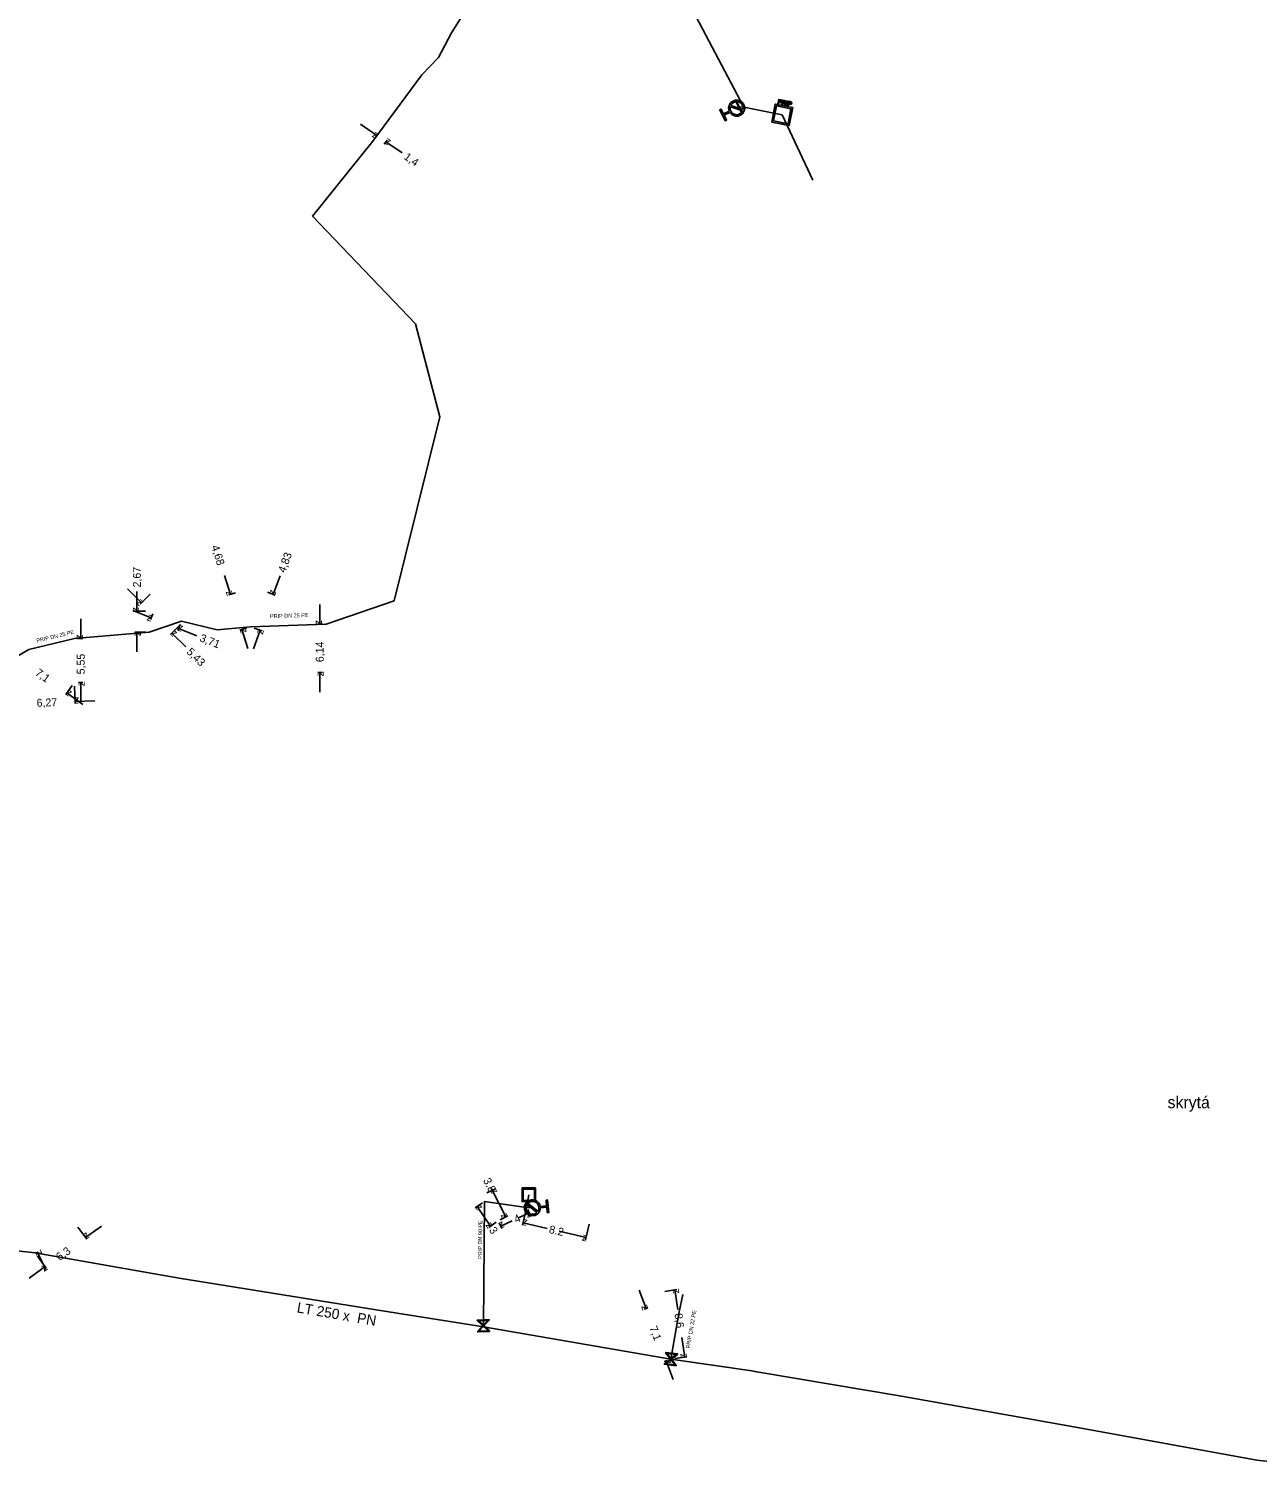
# Model space of a CAD drawing. Extents: x -643842 to -636370, y -1119190 to -1110210.
# Drawn here: x -641528.3 to -641372.7, y -1114327.3 to -1114143.7 of the extents above; entities that cross this region are included whole.
import ezdxf

# ---------------------------------------------------------------- set-up
doc = ezdxf.new("R2010")
doc.units = 0
for name, color, linetype in [('22', 7, 'Continuous'), ('7', 7, 'Continuous'), ('Default', 7, 'Continuous'), ('Level 10', 7, 'Continuous'), ('Level 16', 7, 'Continuous'), ('Level 18', 7, 'Continuous'), ('Level 20', 7, 'Continuous'), ('Level 21', 7, 'Continuous'), ('Level 23', 7, 'Continuous'), ('Level 33', 7, 'Continuous')]:
    doc.layers.add(name, color=color, linetype=linetype)

msp = doc.modelspace()

# ---------------------------------------------------------------- linework, layer by layer
at = {"layer": 'Default'}
for points in [[(-641439.58, -1114154.04), (-641439.72, -1114153.71), (-641439.6, -1114153.36), (-641439.47, -1114152.97), (-641439.09, -1114152.78), (-641438.72, -1114152.6), (-641438.33, -1114152.73), (-641437.94, -1114152.86), (-641437.75, -1114153.24), (-641437.57, -1114153.6), (-641437.7, -1114154), (-641437.83, -1114154.39), (-641438.2, -1114154.57), (-641438.57, -1114154.76), (-641438.97, -1114154.63), (-641439.32, -1114154.52), (-641439.5, -1114154.21)], [(-641439.45, -1114153.51), (-641439.51, -1114153.78), (-641439.38, -1114154.04), (-641439.23, -1114154.35), (-641438.91, -1114154.45), (-641438.59, -1114154.56), (-641438.29, -1114154.41), (-641438.03, -1114154.28), (-641437.91, -1114154.02)], [(-641437.85, -1114153.85), (-641437.79, -1114153.58), (-641437.92, -1114153.32), (-641438.07, -1114153.02), (-641438.39, -1114152.91), (-641438.71, -1114152.8), (-641439.01, -1114152.96), (-641439.27, -1114153.08), (-641439.39, -1114153.34)], [(-641433.12, -1114152.61), (-641433.06, -1114152.62), (-641433.04, -1114152.63), (-641433, -1114152.65), (-641432.97, -1114152.67), (-641432.95, -1114152.69), (-641432.94, -1114152.73), (-641432.93, -1114152.77), (-641432.94, -1114152.81), (-641432.95, -1114152.89), (-641433, -1114152.93), (-641433.06, -1114152.97), (-641433.18, -1114152.94)], [(-641433.16, -1114152.88), (-641433.09, -1114152.89), (-641433.06, -1114152.87), (-641433.02, -1114152.85), (-641433.01, -1114152.8), (-641433.01, -1114152.76), (-641433.02, -1114152.74), (-641433.03, -1114152.71), (-641433.06, -1114152.7), (-641433.08, -1114152.69), (-641433.13, -1114152.68)], [(-641432.59, -1114153.17), (-641432.61, -1114153.12), (-641432.63, -1114153.09), (-641432.64, -1114153.05), (-641432.66, -1114153.04), (-641432.67, -1114153.03), (-641432.69, -1114153.02), (-641432.7, -1114153.01), (-641432.73, -1114153.01)], [(-641432.64, -1114152.96), (-641432.59, -1114152.97), (-641432.56, -1114152.96), (-641432.53, -1114152.96), (-641432.51, -1114152.94), (-641432.49, -1114152.92), (-641432.49, -1114152.89), (-641432.48, -1114152.85), (-641432.5, -1114152.82), (-641432.53, -1114152.79), (-641432.59, -1114152.78)], [(-641432.58, -1114152.71), (-641432.5, -1114152.73), (-641432.47, -1114152.75), (-641432.43, -1114152.77), (-641432.42, -1114152.82), (-641432.4, -1114152.86), (-641432.41, -1114152.9), (-641432.42, -1114152.97), (-641432.47, -1114153), (-641432.51, -1114153.03), (-641432.6, -1114153.03), (-641432.57, -1114153.05), (-641432.56, -1114153.06), (-641432.53, -1114153.1), (-641432.51, -1114153.15)], [(-641431.86, -1114152.85), (-641431.81, -1114152.87), (-641431.78, -1114152.88), (-641431.74, -1114152.89), (-641431.71, -1114152.92), (-641431.69, -1114152.94), (-641431.68, -1114152.98), (-641431.67, -1114153.02), (-641431.68, -1114153.06), (-641431.69, -1114153.13), (-641431.74, -1114153.17), (-641431.8, -1114153.21), (-641431.92, -1114153.19)], [(-641431.91, -1114153.12), (-641431.83, -1114153.14), (-641431.8, -1114153.12), (-641431.76, -1114153.1), (-641431.75, -1114153.05), (-641431.75, -1114153.01), (-641431.76, -1114152.98), (-641431.77, -1114152.96), (-641431.8, -1114152.94), (-641431.82, -1114152.93), (-641431.87, -1114152.92)], [(-641463.52, -1114292.94), (-641463.52, -1114293.3), (-641463.75, -1114293.58), (-641464.02, -1114293.9), (-641464.43, -1114293.94), (-641464.84, -1114293.98), (-641465.16, -1114293.72), (-641465.48, -1114293.46), (-641465.52, -1114293.04), (-641465.56, -1114292.63), (-641465.3, -1114292.31), (-641465.04, -1114291.99), (-641464.62, -1114291.95), (-641464.21, -1114291.91), (-641463.89, -1114292.17), (-641463.6, -1114292.4), (-641463.54, -1114292.76)], [(-641465.21, -1114292.5), (-641465.36, -1114292.74), (-641465.33, -1114293.02), (-641465.3, -1114293.36), (-641465.04, -1114293.57), (-641464.78, -1114293.79), (-641464.44, -1114293.75), (-641464.16, -1114293.73), (-641463.96, -1114293.53)], [(-641463.84, -1114293.39), (-641463.69, -1114293.16), (-641463.71, -1114292.87), (-641463.75, -1114292.53), (-641464.01, -1114292.32), (-641464.27, -1114292.1), (-641464.6, -1114292.14), (-641464.89, -1114292.16), (-641465.09, -1114292.36)]]:
    msp.add_open_spline(points, degree=3, dxfattribs=at)
at = {"layer": 'Level 10'}
for points in [[(-641486.28, -1114155.7), (-641484.22, -1114157.13)], [(-641484.44, -1114157.43), (-641484.08, -1114156.92)], [(-641483.29, -1114158.23), (-641482.93, -1114157.72)], [(-641481.02, -1114159.35), (-641483.07, -1114157.93)], [(-641503.52, -1114212.87), (-641502.76, -1114215.25)], [(-641496.49, -1114212.9), (-641497.35, -1114215.25)], [(-641515.82, -1114214.57), (-641514.05, -1114216.33)], [(-641514.62, -1114214.87), (-641514.62, -1114217.37)], [(-641512.96, -1114215.23), (-641514.22, -1114216.51)], [(-641502.12, -1114215.04), (-641502.99, -1114215.32)], [(-641498.09, -1114214.98), (-641497.11, -1114215.34)], [(-641515.13, -1114217.29), (-641512.8, -1114218.21)], [(-641513.55, -1114217.37), (-641514.87, -1114217.37)], [(-641512.61, -1114217.73), (-641512.9, -1114218.44)], [(-641491.46, -1114216.52), (-641491.46, -1114219.02)], [(-641521.73, -1114218.35), (-641521.73, -1114220.85)], [(-641509.1, -1114219.06), (-641510.37, -1114220.33)], [(-641509.17, -1114219.1), (-641509.45, -1114219.81)], [(-641507.03, -1114220.5), (-641509.36, -1114219.58)], [(-641500.69, -1114219.5), (-641501.57, -1114219.78)], [(-641500.57, -1114222.09), (-641501.33, -1114219.7)], [(-641499.86, -1114222.14), (-641499, -1114219.79)], [(-641499.75, -1114219.52), (-641498.77, -1114219.87)], [(-641491.13, -1114219.02), (-641491.71, -1114219.02)], [(-641522.03, -1114220.85), (-641521.48, -1114220.85)], [(-641513.55, -1114220.04), (-641514.87, -1114220.04)], [(-641514.62, -1114222.54), (-641514.62, -1114220.04)], [(-641508.42, -1114221.92), (-641510.19, -1114220.16)], [(-641491.13, -1114225.16), (-641491.71, -1114225.16)], [(-641491.46, -1114227.66), (-641491.46, -1114225.16)], [(-641522.82, -1114226.8), (-641523.64, -1114227.94)], [(-641522.51, -1114226.9), (-641522.42, -1114229.06)], [(-641522.03, -1114226.4), (-641521.48, -1114226.4)], [(-641521.73, -1114228.9), (-641521.73, -1114226.4)], [(-641521.46, -1114229.2), (-641523.49, -1114227.73)], [(-641519.94, -1114228.72), (-641522.43, -1114228.81)], [(-641470.31, -1114291.06), (-641469.34, -1114290.57)], [(-641469.78, -1114290.37), (-641469.61, -1114290.71)], [(-641469.61, -1114290.71), (-641467.9, -1114294.1)], [(-641470.83, -1114292.3), (-641471.78, -1114292.96)], [(-641469.82, -1114295.25), (-641471.54, -1114292.79)], [(-641465.32, -1114293.18), (-641465.77, -1114295.15)], [(-641465.12, -1114293.16), (-641464.79, -1114293.86)], [(-641519.1, -1114295.25), (-641521.13, -1114296.71)], [(-641469.12, -1114294.76), (-641470.06, -1114295.42)], [(-641468.74, -1114294.86), (-641468.41, -1114295.57)], [(-641468.6, -1114294.46), (-641467.63, -1114293.97)], [(-641467.07, -1114294.6), (-641468.54, -1114295.29)], [(-641466.27, -1114294.23), (-641464.92, -1114293.59)], [(-641462.67, -1114295.56), (-641465.71, -1114294.86)], [(-641457.33, -1114295.02), (-641457.78, -1114297)], [(-641522.08, -1114295.39), (-641520.98, -1114296.91)], [(-641461.13, -1114295.91), (-641457.72, -1114296.7)], [(-641526.15, -1114300.78), (-641527.25, -1114298.54)], [(-641527.04, -1114298.43), (-641527.03, -1114298.43)], [(-641528.27, -1114301.84), (-641526.24, -1114300.39)], [(-641527.2, -1114299.06), (-641526.1, -1114300.59)], [(-641451.02, -1114303.38), (-641450.12, -1114305.71)], [(-641447.74, -1114303.53), (-641446.23, -1114303.3)], [(-641446.11, -1114305.82), (-641446.48, -1114303.34)], [(-641449.99, -1114305.66), (-641450.36, -1114305.8)], [(-641445.59, -1114309.37), (-641445.22, -1114311.85)], [(-641446.48, -1114312.03), (-641444.97, -1114311.81)], [(-641447.44, -1114312.29), (-641447.81, -1114312.43)], [(-641446.68, -1114314.67), (-641447.58, -1114312.34)]]:
    msp.add_lwpolyline(points, dxfattribs=at)
at = {"layer": 'Level 16'}
for points in [[(-641438.66, -1114152.8), (-641437.99, -1114154.14), (-641438.08, -1114154.18), (-641438.75, -1114152.84), (-641438.66, -1114152.8)], [(-641469.95, -1114308.61), (-641471.45, -1114308.67), (-641471.45, -1114308.6), (-641471.36, -1114308.51), (-641470.79, -1114307.89), (-641471.5, -1114307.23), (-641471.51, -1114307.17), (-641470.01, -1114307.11), (-641470.01, -1114307.18), (-641470.67, -1114307.89), (-641470.05, -1114308.46), (-641469.95, -1114308.54), (-641469.95, -1114308.61)], [(-641471.35, -1114307.25), (-641470.73, -1114307.83), (-641470.16, -1114307.21), (-641471.35, -1114307.25)], [(-641470.11, -1114308.52), (-641470.73, -1114307.95), (-641471.3, -1114308.57), (-641470.11, -1114308.52)], [(-641446.32, -1114312.94), (-641447.81, -1114312.76), (-641447.8, -1114312.69), (-641447.7, -1114312.62), (-641447.04, -1114312.1), (-641447.63, -1114311.34), (-641447.63, -1114311.27), (-641446.14, -1114311.46), (-641446.15, -1114311.52), (-641446.91, -1114312.12), (-641446.4, -1114312.78), (-641446.31, -1114312.88), (-641446.32, -1114312.94)], [(-641447.49, -1114311.38), (-641446.97, -1114312.05), (-641446.3, -1114311.53), (-641447.49, -1114311.38)], [(-641446.47, -1114312.83), (-641446.98, -1114312.17), (-641447.64, -1114312.69), (-641446.47, -1114312.83)]]:
    msp.add_lwpolyline(points, dxfattribs=at)
at = {"layer": 'Level 18'}
for points in [[(-641431.54, -1114153.6), (-641431.99, -1114155.88), (-641434.21, -1114155.45), (-641433.76, -1114153.17), (-641431.54, -1114153.6)], [(-641433.61, -1114153.4), (-641433.98, -1114155.29), (-641432.14, -1114155.65), (-641431.77, -1114153.76), (-641433.61, -1114153.4)], [(-641433.44, -1114153.13), (-641433.33, -1114152.57), (-641433.12, -1114152.61)], [(-641433.18, -1114152.94), (-641433.32, -1114152.91), (-641433.37, -1114153.14), (-641433.44, -1114153.13)], [(-641433.13, -1114152.68), (-641433.27, -1114152.65), (-641433.31, -1114152.85)], [(-641433.31, -1114152.85), (-641433.16, -1114152.88)], [(-641432.94, -1114153.23), (-641432.83, -1114152.66), (-641432.58, -1114152.71)], [(-641432.73, -1114153.01), (-641432.81, -1114152.99), (-641432.86, -1114153.24), (-641432.94, -1114153.23)], [(-641432.59, -1114152.78), (-641432.77, -1114152.74), (-641432.8, -1114152.93)], [(-641432.8, -1114152.93), (-641432.64, -1114152.96)], [(-641432.51, -1114153.15), (-641432.44, -1114153.32), (-641432.54, -1114153.31), (-641432.59, -1114153.17)], [(-641432.37, -1114153.34), (-641432.26, -1114152.78), (-641432.19, -1114152.79), (-641432.29, -1114153.35), (-641432.37, -1114153.34)], [(-641432.18, -1114153.38), (-641432.07, -1114152.81), (-641431.86, -1114152.85)], [(-641431.92, -1114153.19), (-641432.06, -1114153.16), (-641432.11, -1114153.39), (-641432.18, -1114153.38)], [(-641431.87, -1114152.92), (-641432.01, -1114152.89), (-641432.05, -1114153.1)], [(-641432.05, -1114153.1), (-641431.91, -1114153.12)], [(-641464.13, -1114290.42), (-641464.13, -1114292.16), (-641465.82, -1114292.16), (-641465.82, -1114290.42), (-641464.13, -1114290.42)], [(-641465.68, -1114290.57), (-641465.68, -1114292.01), (-641464.27, -1114292.01), (-641464.27, -1114290.57), (-641465.68, -1114290.57)]]:
    msp.add_lwpolyline(points, dxfattribs=at)
at = {"layer": 'Level 21'}
for points in [[(-641457.53, -1114115.49), (-641457.43, -1114115.74), (-641447.29, -1114135.38), (-641446.98, -1114135.99), (-641437.76, -1114153.57), (-641432.87, -1114154.52)], [(-641349.91, -1114327.29), (-641351.84, -1114327.15), (-641372.75, -1114324.91), (-641395.95, -1114320.67), (-641417.77, -1114316.82), (-641436.1, -1114313.72), (-641436.74, -1114313.61), (-641446.97, -1114312.11), (-641470.72, -1114308.04), (-641484.31, -1114305.87), (-641509.25, -1114301.85), (-641527.49, -1114298.65), (-641532.99, -1114298.05), (-641533, -1114298.05)]]:
    msp.add_lwpolyline(points, dxfattribs=at)
at = {"layer": 'Level 23'}
for points in [[(-641458.89, -1114116.02), (-641458.87, -1114116.12), (-641459.97, -1114120.78), (-641462.47, -1114124.6), (-641474.77, -1114144.15), (-641476.4, -1114147.27), (-641478.54, -1114149.45), (-641484.72, -1114157.84), (-641492.36, -1114167.36), (-641479.34, -1114180.99), (-641476.26, -1114192.79), (-641482.04, -1114216.07), (-641490.63, -1114219.02), (-641500.21, -1114219.35), (-641504.45, -1114219.75), (-641508.98, -1114218.64), (-641513.05, -1114220.04), (-641522.53, -1114220.85), (-641528.29, -1114222.24)], [(-641437.76, -1114153.57), (-641438.37, -1114153.49), (-641438.65, -1114153.68)], [(-641432.87, -1114154.52), (-641429, -1114162.8)], [(-641528.29, -1114222.24), (-641536.38, -1114226.93)], [(-641470.72, -1114308.04), (-641470.73, -1114307.89), (-641470.59, -1114292.13), (-641465.25, -1114292.89), (-641464.97, -1114291.29)], [(-641465.25, -1114292.89), (-641464.89, -1114292.9), (-641464.53, -1114292.95)], [(-641446.97, -1114312.11), (-641445.93, -1114306.11), (-641445.49, -1114303.93)]]:
    msp.add_lwpolyline(points, dxfattribs=at)
at = {"layer": 'Level 33'}
for points in [[(-641439.5, -1114154.21), (-641440.23, -1114154.57), (-641439.93, -1114155.19), (-641440.09, -1114155.27), (-641440.79, -1114153.87), (-641440.62, -1114153.79), (-641440.32, -1114154.41), (-641439.58, -1114154.04)], [(-641437.91, -1114154.02), (-641439.45, -1114153.51)], [(-641439.39, -1114153.34), (-641437.85, -1114153.85)], [(-641463.96, -1114293.53), (-641465.21, -1114292.5)], [(-641465.09, -1114292.36), (-641463.84, -1114293.39)], [(-641463.54, -1114292.76), (-641462.73, -1114292.68), (-641462.79, -1114291.99), (-641462.61, -1114291.97), (-641462.46, -1114293.53), (-641462.64, -1114293.55), (-641462.71, -1114292.86), (-641463.52, -1114292.94)]]:
    msp.add_lwpolyline(points, dxfattribs=at)

# ---------------------------------------------------------------- texts
at = {"layer": '22'}
for s, rotation, p in [('PRIP DN 25 PE', 1.9581, (-641497.75, -1114218.28)), ('PRIP DN 25 PE', 13.6321, (-641527.28, -1114221.38)), ('PRIP DN 90 PE', 89.4837, (-641470.92, -1114299.41)), ('PRIP DN 32 PE', 80.0844, (-641444.59, -1114310.77))]:
    msp.add_text(s, height=0.5, rotation=rotation, dxfattribs=at).set_placement(p)
at = {"layer": '7'}
msp.add_text('skrytá', height=1.5, dxfattribs=at).set_placement((-641384.07, -1114280.33))
at = {"layer": 'Level 10'}
for s, rotation, p in [('z', 325.267, (-641484.92, -1114157.25)), ('z', 145.267, (-641482.38, -1114157.8)), ('1,4', 325.267, (-641480.89, -1114160.05)), ('4,68', 287.7305, (-641505.21, -1114209.2)), ('4,83', 69.9647, (-641495.85, -1114212.6)), ('2,67', 90, (-641514.12, -1114214.37)), ('z', 315.2413, (-641514.75, -1114216.34)), ('z', 287.7305, (-641503.38, -1114214.92)), ('z', 249.9647, (-641497.65, -1114214.61)), ('z', 270, (-641515.12, -1114216.87)), ('z', 338.3512, (-641513.45, -1114218.49)), ('z', 90, (-641514.12, -1114220.54)), ('z', 135.2413, (-641509.49, -1114220.15)), ('z', 158.3512, (-641508.71, -1114219.3)), ('z', 107.7305, (-641500.7, -1114220.03)), ('z', 69.9647, (-641498.71, -1114220.43)), ('z', 270, (-641491.96, -1114218.52)), ('z', 270, (-641522.23, -1114220.35)), ('3,71', 338.3512, (-641506.75, -1114221.15)), ('6,14', 90, (-641490.96, -1114223.84)), ('5,55', 90, (-641521.23, -1114225.38)), ('5,43', 315.2413, (-641508.41, -1114222.62)), ('7,1', 324.1971, (-641527.59, -1114225.39)), ('z', 90, (-641490.96, -1114225.66)), ('z', 144.1971, (-641522.79, -1114227.62)), ('z', 90, (-641521.23, -1114226.9)), ('6,27', 2.2179, (-641527.3, -1114229.5)), ('z', 182.2179, (-641521.95, -1114228.3)), ('3.8', 296.7403, (-641470.8, -1114289.46)), ('z', 116.7403, (-641468.94, -1114290.93)), ('z', 124.9138, (-641470.84, -1114292.92)), ('z', 25.1943, (-641465.16, -1114294.26)), ('z', 304.9138, (-641470.51, -1114295.13)), ('z', 205.1943, (-641468.3, -1114294.63)), ('z', 296.7404, (-641468.57, -1114293.88)), ('4', 25.1943, (-641466.58, -1114294.93)), ('z', 167.0111, (-641465.11, -1114294.49)), ('8.2', 347.0111, (-641462.49, -1114296.12)), ('z', 215.6794, (-641521.01, -1114296.01)), ('3', 304.9138, (-641470.06, -1114295.78)), ('z', 347.0112, (-641458.31, -1114297.08)), ('z', 116.1903, (-641526.58, -1114298.77)), ('6,3', 35.6794, (-641524.42, -1114299.7)), ('z', 35.6794, (-641526.36, -1114301.08)), ('z', 98.3985, (-641445.91, -1114303.76)), ('z', 291.0146, (-641450.77, -1114305.42)), ('7,1', 291.0146, (-641449.73, -1114308.13)), ('8,6', 278.3985, (-641446.53, -1114306.39)), ('z', 278.3985, (-641445.79, -1114311.43)), ('z', 111.0146, (-641446.93, -1114312.63))]:
    msp.add_text(s, height=1, rotation=rotation, dxfattribs=at).set_placement(p)
at = {"layer": 'Level 20'}
msp.add_text('LT 250 x  PN ', height=1.3, rotation=350.2245, dxfattribs=at).set_placement((-641494.42, -1114306.18))

doc.saveas('drawing.dxf')
